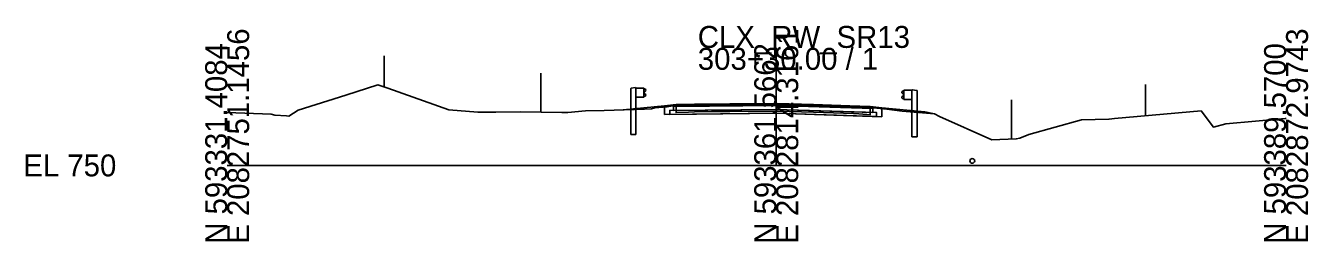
# Model space of a CAD drawing. Extents: x -26 to 2138, y -10 to 4518.
# Drawn here: x 974.3 to 1137.8, y 2490.3 to 2517.8 of the extents above; entities that cross this region are included whole.
import ezdxf

# ---------------------------------------------------------------- set-up
doc = ezdxf.new("R2010")
doc.units = 0
for name, color, linetype in [('GK_Cells', 7, 'Continuous'), ('MD_P_Surface_Aggregate_Base', 7, 'Continuous'), ('MD_P_Surface_Asphalt_Concrete_Base', 7, 'Continuous'), ('MD_P_Surface_Asphalt_Concrete_Intermediate_Course', 7, 'Continuous'), ('MD_P_Surface_Asphalt_Concrete_Surface_Course', 7, 'Continuous'), ('MD_X_Asphalt_Pavement', 7, 'Continuous'), ('RD_P_Cells', 7, 'Continuous'), ('RW_P_Esmt_SH', 7, 'Continuous'), ('RW_X_Esmt_SH', 7, 'Continuous'), ('SC_Scratch1', 7, 'Continuous'), ('UT_X_Water', 7, 'Continuous'), ('XS_P_Finished_Grade', 7, 'Continuous'), ('XS_P_Subgrade', 7, 'Continuous'), ('XS_X_Ground_Line', 7, 'Continuous')]:
    doc.layers.add(name, color=color, linetype=linetype)

msp = doc.modelspace()

# ---------------------------------------------------------------- linework, layer by layer
at = {"layer": 'GK_Cells'}
for p, q in [((1070, 2500), (1070, 2515)), ((1000, 2500), (1070, 2500)), ((1070, 2500), (1135, 2500))]:
    msp.add_line(p, q, dxfattribs=at)
at = {"layer": 'MD_P_Surface_Aggregate_Base'}
for points in [[(1070, 2507.15), (1070, 2506.65), (1056.42, 2506.51), (1056.42, 2507.01), (1070, 2507.15)], [(1070, 2507.15), (1070, 2506.65), (1082.8, 2506.24), (1082.8, 2506.74), (1070, 2507.15)]]:
    msp.add_lwpolyline(points, dxfattribs=at)
at = {"layer": 'MD_P_Surface_Asphalt_Concrete_Base'}
for points in [[(1070, 2507.65), (1070, 2507.15), (1056.92, 2507.02), (1056.92, 2507.52), (1070, 2507.65)], [(1082.3, 2507.25), (1082.3, 2506.75), (1070, 2507.15), (1070, 2507.65)]]:
    msp.add_lwpolyline(points, dxfattribs=at)
at = {"layer": 'MD_P_Surface_Asphalt_Concrete_Intermediate_Course'}
for points in [[(1070, 2507.79), (1070, 2507.65), (1057.25, 2507.52), (1057.25, 2507.67), (1070, 2507.79)], [(1070, 2507.65), (1070, 2507.79)]]:
    msp.add_lwpolyline(points, dxfattribs=at)
at = {"layer": 'MD_P_Surface_Asphalt_Concrete_Surface_Course'}
for points in [[(1070, 2507.9), (1070, 2507.79), (1057.25, 2507.67), (1057.25, 2507.77), (1070, 2507.9)], [(1070, 2507.79), (1070, 2507.9)]]:
    msp.add_lwpolyline(points, dxfattribs=at)
at = {"layer": 'MD_X_Asphalt_Pavement'}
msp.add_lwpolyline([(1058.82, 2507.73), (1057.24, 2507.69), (1057.24, 2506.74), (1058.82, 2506.78), (1059.58, 2506.85), (1061.74, 2506.87), (1064.1, 2506.9), (1069.91, 2506.94), (1070.14, 2506.94), (1074.76, 2506.8), (1079.85, 2506.62), (1080.53, 2506.6), (1081.54, 2506.49), (1081.96, 2506.45), (1081.96, 2507.41), (1081.54, 2507.44), (1080.53, 2507.56), (1079.85, 2507.58), (1074.76, 2507.76), (1070.14, 2507.9), (1069.91, 2507.9), (1064.1, 2507.85), (1061.74, 2507.83), (1059.58, 2507.8), (1058.82, 2507.73)], dxfattribs=at)
at = {"layer": 'RD_P_Cells'}
for p, q in [((1051.5, 2509.84), (1051.45, 2509.82)), ((1051.45, 2503.93), (1051.45, 2509.82)), ((1052.04, 2509.93), (1051.5, 2509.84)), ((1052.12, 2509.88), (1052.04, 2509.93)), ((1053.12, 2509.88), (1052.12, 2509.88)), ((1052.12, 2503.93), (1052.12, 2509.88)), ((1053.12, 2508.7), (1052.12, 2508.7)), ((1053.12, 2508.7), (1053.12, 2509.88)), ((1053.21, 2509.79), (1053.12, 2509.8)), ((1053.12, 2508.78), (1053.21, 2508.8)), ((1053.13, 2509.29), (1053.13, 2509.34)), ((1053.13, 2509.24), (1053.13, 2509.29)), ((1053.16, 2509.4), (1053.37, 2509.54)), ((1053.37, 2509.04), (1053.16, 2509.18)), ((1053.37, 2509.67), (1053.21, 2509.79)), ((1053.21, 2508.8), (1053.37, 2508.91)), ((1086.03, 2509.4), (1086.19, 2509.51)), ((1086.24, 2509.13), (1086.03, 2509.27)), ((1086.03, 2508.76), (1086.24, 2508.91)), ((1086.19, 2508.52), (1086.03, 2508.64)), ((1086.19, 2509.51), (1086.28, 2509.53)), ((1086.27, 2509.02), (1086.27, 2509.06)), ((1086.27, 2508.97), (1086.27, 2509.02)), ((1086.28, 2508.42), (1086.28, 2509.61)), ((1086.28, 2509.61), (1087.28, 2509.61)), ((1087.28, 2509.61), (1087.36, 2509.65)), ((1087.28, 2503.65), (1087.28, 2509.61)), ((1087.36, 2509.65), (1087.9, 2509.57)), ((1087.9, 2509.57), (1087.95, 2509.55)), ((1087.95, 2503.65), (1087.95, 2509.55)), ((1086.28, 2508.51), (1086.19, 2508.52)), ((1086.28, 2508.42), (1087.28, 2508.42)), ((1052.12, 2503.93), (1051.45, 2503.93)), ((1087.28, 2503.65), (1087.95, 2503.65))]:
    msp.add_line(p, q, dxfattribs=at)
for points in [[(1053.14, 2509.35), (1053.14, 2509.23), (1053.13, 2509.23), (1053.13, 2509.35)], [(1053.14, 2509.32), (1053.14, 2509.26), (1053.16, 2509.26), (1053.16, 2509.32)], [(1086.26, 2509.05), (1086.26, 2508.99), (1086.24, 2508.99), (1086.24, 2509.05)], [(1086.26, 2509.08), (1086.26, 2508.96), (1086.27, 2508.96), (1086.27, 2509.08)]]:
    msp.add_lwpolyline(points, close=True, dxfattribs=at)
for centre, start, end in [((1053.21, 2509.34), 124.962, 180), ((1053.21, 2509.24), 180, 235.038), ((1053.32, 2509.61), 304.962, 54.7677), ((1053.32, 2508.97), 304.962, 54.7677), ((1086.08, 2509.33), 125.2323, 235.038), ((1086.08, 2508.7), 125.2323, 235.038), ((1086.19, 2509.06), 0, 55.038), ((1086.19, 2508.97), 304.962, 0)]:
    msp.add_arc(centre, 0.0781, start, end, dxfattribs=at)
at = {"layer": 'RW_P_Esmt_SH'}
for p, q in [((1020, 2510), (1020, 2514)), ((1117.08, 2506.32), (1117.08, 2510.32))]:
    msp.add_line(p, q, dxfattribs=at)
at = {"layer": 'RW_X_Esmt_SH'}
for p, q in [((1040, 2506.79), (1040, 2511.79)), ((1100, 2503.37), (1100, 2508.37))]:
    msp.add_line(p, q, dxfattribs=at)
at = {"layer": 'SC_Scratch1'}
for p, q in [((1057.25, 2507.77), (1055.75, 2507.62)), ((1056.42, 2507.01), (1070, 2507.15)), ((1056.42, 2507.01), (1056.42, 2506.51)), ((1056.92, 2507.52), (1070, 2507.65)), ((1056.92, 2507.52), (1056.92, 2507.02)), ((1057.25, 2507.77), (1070, 2507.9)), ((1057.25, 2507.67), (1070, 2507.79)), ((1057.25, 2507.77), (1057.25, 2507.52)), ((1070, 2507.9), (1081.97, 2507.51)), ((1070, 2507.79), (1081.97, 2507.41)), ((1070, 2507.65), (1082.3, 2507.25)), ((1070, 2507.15), (1082.8, 2506.74)), ((1081.97, 2507.51), (1081.97, 2507.26)), ((1081.97, 2507.51), (1083.47, 2507.36)), ((1082.3, 2507.25), (1082.3, 2506.75)), ((1082.8, 2506.74), (1082.8, 2506.24))]:
    msp.add_line(p, q, dxfattribs=at)
at = {"layer": 'UT_X_Water'}
msp.add_circle((1095, 2500.58), 0.3, dxfattribs=at)
at = {"layer": 'XS_P_Finished_Grade'}
for p, q in [((1055.75, 2507.62), (1050.49, 2507.09)), ((1083.47, 2507.36), (1088.95, 2506.82)), ((1088.95, 2506.82), (1090.17, 2506.58))]:
    msp.add_line(p, q, dxfattribs=at)
at = {"layer": 'XS_P_Subgrade'}
for p, q in [((1055.75, 2507.62), (1055.75, 2506.5)), ((1083.47, 2507.36), (1083.47, 2506.22)), ((1055.75, 2506.5), (1070, 2506.65)), ((1070, 2506.65), (1083.47, 2506.22))]:
    msp.add_line(p, q, dxfattribs=at)
at = {"layer": 'XS_X_Ground_Line'}
msp.add_lwpolyline([(1000, 2506.77), (1005.61, 2506.53), (1006.07, 2506.42), (1007.58, 2506.32), (1007.85, 2506.3), (1009.03, 2507.05), (1015.12, 2508.96), (1019.19, 2510.27), (1020.49, 2509.84), (1028.27, 2507.11), (1031.97, 2506.79), (1034.02, 2506.81), (1034.25, 2506.81), (1037.37, 2506.83), (1042.68, 2506.75), (1043.42, 2506.75), (1045.7, 2506.97), (1048.06, 2507), (1053.21, 2507.2), (1054.11, 2507.22), (1054.51, 2507.36), (1056.1, 2507.49), (1057.24, 2507.69), (1058.82, 2507.73), (1059.58, 2507.8), (1064.1, 2507.85), (1070.14, 2507.9), (1074.76, 2507.76), (1080.53, 2507.56), (1081.54, 2507.44), (1081.96, 2507.41), (1084.08, 2507.19), (1086.04, 2506.93), (1090.17, 2506.58), (1090.83, 2506.23), (1097.48, 2503.28), (1100.61, 2503.39), (1101.05, 2503.47), (1102.21, 2503.96), (1108.93, 2505.82), (1112.39, 2505.9), (1112.43, 2505.91), (1113.12, 2505.97), (1124.16, 2506.95), (1125.75, 2504.87), (1127.32, 2505.31), (1134.9, 2505.99), (1135, 2505.97)], dxfattribs=at)

# ---------------------------------------------------------------- texts
msp.add_text('-', height=0.0001).set_placement((1000, 2500))
at = {"layer": 'GK_Cells'}
for s, p in [('E 2082751.1456', (1002.8, 2490)), ('E 2082814.3161', (1072.8, 2490)), ('E 2082872.9743', (1137.8, 2490)), ('N 593331.4084', (1000, 2490)), ('N 593361.5662', (1070, 2490)), ('N 593389.5700', (1135, 2490))]:
    msp.add_text(s, height=2.8, rotation=90, dxfattribs=at).set_placement(p)
for s, p in [('CLX_RW_SR13', (1060, 2515)), ('303+30.00 / 1', (1060, 2512.2)), ('EL 750', (974, 2498.6))]:
    msp.add_text(s, height=2.8, dxfattribs=at).set_placement(p)

doc.saveas('drawing.dxf')
